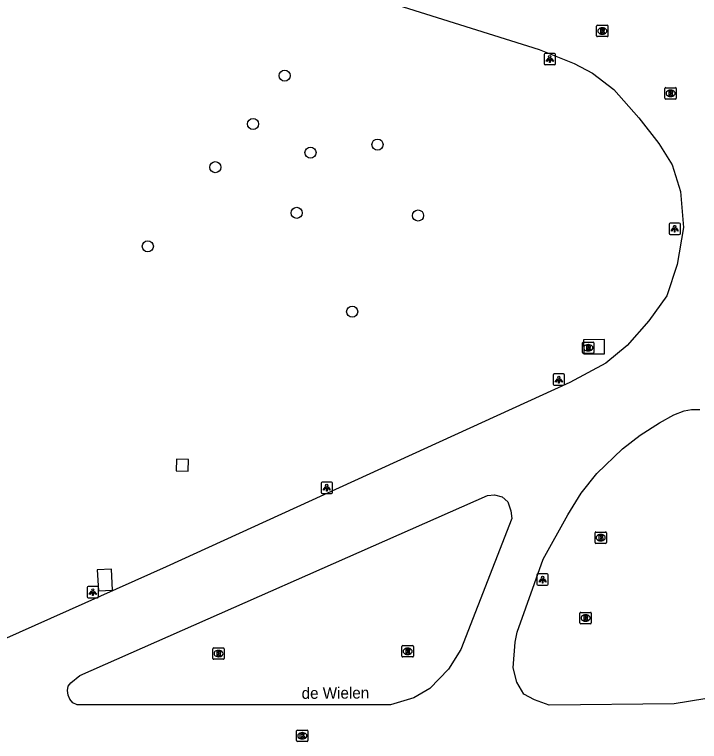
# Model space of a CAD drawing. Extents: x 161477 to 163040, y 383680 to 384868.
# Drawn here: x 161751.9 to 161812.2, y 384190.3 to 384254.4 of the extents above; entities that cross this region are included whole.
import ezdxf

# ---------------------------------------------------------------- set-up
doc = ezdxf.new("R2010")
doc.units = 0
for name, color, linetype in [('IMGEO_Boom', 7, 'Continuous'), ('IMGEO_Brandkraan', 7, 'Continuous'), ('IMGEO_Kolk', 7, 'Continuous'), ('IMGEO_Lage_trafo', 7, 'Continuous'), ('IMGEO_Lichtpunt', 7, 'Continuous'), ('IMGEO_Openbare_ruimte_label', 7, 'Continuous'), ('IMGEO_Rijbaan_lokaal_gesloten', 7, 'Continuous'), ('IMGEO_Rioolput', 7, 'Continuous'), ('IMGEO_Voetpad_gesloten', 7, 'Continuous')]:
    doc.layers.add(name, color=color, linetype=linetype)

msp = doc.modelspace()

# ---------------------------------------------------------------- linework, layer by layer
at = {"layer": 'IMGEO_Boom'}
for centre in [(161775.696, 384248.985), (161772.921, 384244.729), (161783.878, 384242.91), (161777.975, 384242.204), (161769.594, 384240.919), (161776.761, 384236.894), (161787.45, 384236.66), (161763.649, 384233.95), (161781.646, 384228.19)]:
    msp.add_circle(centre, 0.489, dxfattribs=at)
at = {"layer": 'IMGEO_Brandkraan'}
for p, q in [((161803.029, 384207.854), (161803.029, 384208.706)), ((161803.104, 384208.78), (161803.956, 384208.78)), ((161803.517, 384208.56), (161803.542, 384208.56)), ((161804.03, 384208.706), (161804.03, 384207.854)), ((161803.54, 384208), (161803.515, 384208)), ((161803.956, 384207.78), (161803.104, 384207.78))]:
    msp.add_line(p, q, dxfattribs=at)
for points in [[(161803.029, 384207.854), (161803.029, 384208.706)], [(161803.104, 384208.78), (161803.956, 384208.78)], [(161803.377, 384208.48), (161803.377, 384208.08), (161803.59, 384208.08)], [(161803.608, 384208.48), (161803.377, 384208.48)], [(161804.03, 384208.706), (161804.03, 384207.854)], [(161803.556, 384208.399), (161803.502, 384208.399), (161803.502, 384208.323)], [(161803.502, 384208.323), (161803.555, 384208.323)], [(161803.564, 384208.247), (161803.502, 384208.247), (161803.502, 384208.166)], [(161803.502, 384208.166), (161803.564, 384208.166)], [(161803.956, 384207.78), (161803.104, 384207.78)]]:
    msp.add_lwpolyline(points, dxfattribs=at)
for centre, radius, start, end in [((161803.106, 384208.704), 0.0765, 91.55205, 178.44795), ((161803.106, 384208.704), 0.0765, 91.55205, 178.44795), ((161803.612, 384208.335), 0.145, 59.4692, 91.53667), ((161803.637, 384208.382), 0.0922, 285.51372, 58.15012), ((161803.954, 384208.704), 0.0765, 1.55205, 88.44795), ((161803.954, 384208.704), 0.0765, 1.55205, 88.44795), ((161803.106, 384207.856), 0.0765, 181.55205, 268.44795), ((161803.106, 384207.856), 0.0765, 181.55205, 268.44795), ((161803.557, 384208.361), 0.0379, 267.82845, 90.93552), ((161803.565, 384208.206), 0.0404, 269.87594, 90.50774), ((161803.596, 384208.331), 0.251, 268.66757, 293.53466), ((161803.642, 384208.19), 0.105, 301.31148, 78.98903), ((161803.954, 384207.856), 0.0765, 271.55205, 358.44795), ((161803.954, 384207.856), 0.0765, 271.55205, 358.44795)]:
    msp.add_arc(centre, radius, start, end, dxfattribs=at)
for centre, major_axis, ratio, start_param, end_param in [((161803.516, 384208.28), (-0.387, 0.002), 0.722429, 4.712389, 7.853982), ((161803.541, 384208.28), (-0.39, 0.002), 0.717154, 1.570796, 4.712389)]:
    msp.add_ellipse(centre, major_axis=major_axis, ratio=ratio, start_param=start_param, end_param=end_param, dxfattribs=at)
at = {"layer": 'IMGEO_Kolk'}
for p, q in [((161776.752, 384190.402), (161776.752, 384191.254)), ((161776.827, 384191.328), (161777.679, 384191.328)), ((161777.753, 384191.254), (161777.753, 384190.402)), ((161777.263, 384190.548), (161777.238, 384190.548)), ((161777.24, 384191.108), (161777.265, 384191.108)), ((161777.679, 384190.328), (161776.827, 384190.328))]:
    msp.add_line(p, q, dxfattribs=at)
for points in [[(161776.752, 384190.402), (161776.752, 384191.254)], [(161776.827, 384191.328), (161777.679, 384191.328)], [(161777.753, 384191.254), (161777.753, 384190.402)], [(161777.073, 384191.028), (161777.196, 384191.028), (161777.196, 384190.877), (161777.326, 384191.028), (161777.49, 384191.028), (161777.344, 384190.877), (161777.497, 384190.628), (161777.345, 384190.628), (161777.26, 384190.792), (161777.196, 384190.725), (161777.196, 384190.628), (161777.073, 384190.628), (161777.073, 384191.028)], [(161777.679, 384190.328), (161776.827, 384190.328)]]:
    msp.add_lwpolyline(points, dxfattribs=at)
for centre, start, end in [((161776.829, 384191.252), 91.55205, 178.44795), ((161776.829, 384191.252), 91.55205, 178.44795), ((161777.677, 384191.252), 1.55205, 88.44795), ((161777.677, 384191.252), 1.55205, 88.44795), ((161776.829, 384190.404), 181.55205, 268.44795), ((161776.829, 384190.404), 181.55205, 268.44795), ((161777.677, 384190.404), 271.55205, 358.44795), ((161777.677, 384190.404), 271.55205, 358.44795)]:
    msp.add_arc(centre, 0.0765, start, end, dxfattribs=at)
for centre, major_axis, ratio, start_param, end_param in [((161777.239, 384190.828), (-0.387, 0.002), 0.722429, 4.712389, 7.853982), ((161777.264, 384190.828), (-0.39, 0.002), 0.717154, 1.570796, 4.712389)]:
    msp.add_ellipse(centre, major_axis=major_axis, ratio=ratio, start_param=start_param, end_param=end_param, dxfattribs=at)
at = {"layer": 'IMGEO_Lage_trafo'}
for points in [[(161802.028, 384224.465), (161803.866, 384224.489), (161803.85, 384225.739), (161802.012, 384225.715), (161802.028, 384224.465)], [(161759.307, 384203.601), (161760.555, 384203.67), (161760.452, 384205.503), (161759.204, 384205.434), (161759.307, 384203.601)]]:
    msp.add_lwpolyline(points, dxfattribs=at)
at = {"layer": 'IMGEO_Lichtpunt'}
for p, q in [((161798.546, 384250.852), (161798.546, 384250.045)), ((161798.546, 384250.852), (161798.546, 384250.045)), ((161799.448, 384250.947), (161798.64, 384250.947)), ((161799.448, 384250.947), (161798.64, 384250.947)), ((161799.542, 384250.045), (161799.542, 384250.852)), ((161799.542, 384250.045), (161799.542, 384250.852)), ((161798.64, 384249.951), (161799.448, 384249.951)), ((161798.64, 384249.951), (161799.448, 384249.951)), ((161810.448, 384235.994), (161809.64, 384235.994)), ((161810.448, 384235.994), (161809.64, 384235.994)), ((161809.546, 384235.899), (161809.546, 384235.092)), ((161809.546, 384235.899), (161809.546, 384235.092)), ((161810.542, 384235.092), (161810.542, 384235.899)), ((161810.542, 384235.092), (161810.542, 384235.899)), ((161809.64, 384234.998), (161810.448, 384234.998)), ((161809.64, 384234.998), (161810.448, 384234.998)), ((161799.344, 384222.609), (161799.344, 384221.802)), ((161799.344, 384222.609), (161799.344, 384221.802)), ((161800.246, 384222.704), (161799.438, 384222.704)), ((161800.246, 384222.704), (161799.438, 384222.704)), ((161800.34, 384221.802), (161800.34, 384222.609)), ((161800.34, 384221.802), (161800.34, 384222.609)), ((161799.438, 384221.708), (161800.246, 384221.708)), ((161799.438, 384221.708), (161800.246, 384221.708)), ((161778.909, 384213.087), (161778.909, 384212.28)), ((161778.909, 384213.087), (161778.909, 384212.28)), ((161779.811, 384213.182), (161779.003, 384213.182)), ((161779.811, 384213.182), (161779.003, 384213.182)), ((161779.905, 384212.28), (161779.905, 384213.087)), ((161779.905, 384212.28), (161779.905, 384213.087)), ((161779.003, 384212.186), (161779.811, 384212.186)), ((161779.003, 384212.186), (161779.811, 384212.186)), ((161797.917, 384204.993), (161797.917, 384204.186)), ((161797.917, 384204.993), (161797.917, 384204.186)), ((161798.819, 384205.088), (161798.011, 384205.088)), ((161798.819, 384205.088), (161798.011, 384205.088)), ((161798.913, 384204.186), (161798.913, 384204.993)), ((161798.913, 384204.186), (161798.913, 384204.993)), ((161759.213, 384203.985), (161758.405, 384203.985)), ((161759.213, 384203.985), (161758.405, 384203.985)), ((161798.011, 384204.092), (161798.819, 384204.092)), ((161798.011, 384204.092), (161798.819, 384204.092)), ((161758.311, 384203.89), (161758.311, 384203.083)), ((161758.311, 384203.89), (161758.311, 384203.083)), ((161759.307, 384203.083), (161759.307, 384203.89)), ((161759.307, 384203.083), (161759.307, 384203.89)), ((161758.405, 384202.989), (161759.213, 384202.989)), ((161758.405, 384202.989), (161759.213, 384202.989))]:
    msp.add_line(p, q, dxfattribs=at)
for points in [[(161798.92, 384250.516), (161798.959, 384250.488), (161798.771, 384250.226), (161798.733, 384250.253), (161798.92, 384250.516)], [(161799.022, 384250.468), (161799.069, 384250.468), (161799.069, 384250.146), (161799.022, 384250.146), (161799.022, 384250.468)], [(161799.132, 384250.488), (161799.17, 384250.515), (161799.357, 384250.253), (161799.318, 384250.225), (161799.132, 384250.488)], [(161809.92, 384235.563), (161809.959, 384235.535), (161809.771, 384235.273), (161809.733, 384235.3), (161809.92, 384235.563)], [(161810.022, 384235.515), (161810.069, 384235.515), (161810.069, 384235.193), (161810.022, 384235.193), (161810.022, 384235.515)], [(161810.132, 384235.535), (161810.17, 384235.562), (161810.357, 384235.3), (161810.318, 384235.272), (161810.132, 384235.535)], [(161799.718, 384222.273), (161799.757, 384222.245), (161799.569, 384221.983), (161799.531, 384222.01), (161799.718, 384222.273)], [(161799.82, 384222.225), (161799.867, 384222.225), (161799.867, 384221.903), (161799.82, 384221.903), (161799.82, 384222.225)], [(161799.93, 384222.245), (161799.968, 384222.272), (161800.155, 384222.01), (161800.116, 384221.982), (161799.93, 384222.245)], [(161779.283, 384212.751), (161779.322, 384212.723), (161779.134, 384212.461), (161779.096, 384212.488), (161779.283, 384212.751)], [(161779.385, 384212.703), (161779.432, 384212.703), (161779.432, 384212.381), (161779.385, 384212.381), (161779.385, 384212.703)], [(161779.495, 384212.723), (161779.533, 384212.75), (161779.72, 384212.488), (161779.681, 384212.46), (161779.495, 384212.723)], [(161798.291, 384204.657), (161798.33, 384204.629), (161798.142, 384204.367), (161798.104, 384204.394), (161798.291, 384204.657)], [(161798.503, 384204.629), (161798.541, 384204.656), (161798.728, 384204.394), (161798.689, 384204.366), (161798.503, 384204.629)], [(161798.393, 384204.609), (161798.44, 384204.609), (161798.44, 384204.287), (161798.393, 384204.287), (161798.393, 384204.609)], [(161758.685, 384203.554), (161758.724, 384203.526), (161758.536, 384203.264), (161758.498, 384203.291), (161758.685, 384203.554)], [(161758.787, 384203.506), (161758.834, 384203.506), (161758.834, 384203.184), (161758.787, 384203.184), (161758.787, 384203.506)], [(161758.897, 384203.526), (161758.935, 384203.553), (161759.122, 384203.291), (161759.083, 384203.263), (161758.897, 384203.526)]]:
    msp.add_lwpolyline(points, dxfattribs=at)
for centre in [(161799.045, 384250.65), (161810.045, 384235.697), (161799.843, 384222.407), (161779.408, 384212.885), (161798.416, 384204.791), (161758.81, 384203.688)]:
    msp.add_circle(centre, 0.0994, dxfattribs=at)
for centre, start, end in [((161798.64, 384250.852), 90, 180), ((161798.64, 384250.852), 90, 180), ((161799.448, 384250.852), 0, 90), ((161799.448, 384250.852), 0, 90), ((161798.64, 384250.045), 180, 270), ((161798.64, 384250.045), 180, 270), ((161799.448, 384250.045), 270, 0), ((161799.448, 384250.045), 270, 360), ((161809.64, 384235.899), 90, 180), ((161809.64, 384235.899), 90, 180), ((161810.448, 384235.899), 0, 90), ((161810.448, 384235.899), 0, 90), ((161809.64, 384235.092), 180, 270), ((161809.64, 384235.092), 180, 270), ((161810.448, 384235.092), 270, 0), ((161810.448, 384235.092), 270, 360), ((161799.438, 384222.609), 90, 180), ((161799.438, 384222.609), 90, 180), ((161800.246, 384222.609), 0, 90), ((161800.246, 384222.609), 0, 90), ((161799.438, 384221.802), 180, 270), ((161799.438, 384221.802), 180, 270), ((161800.246, 384221.802), 270, 0), ((161800.246, 384221.802), 270, 360), ((161779.003, 384213.087), 90, 180), ((161779.003, 384213.087), 90, 180), ((161779.811, 384213.087), 0, 90), ((161779.811, 384213.087), 0, 90), ((161779.003, 384212.28), 180, 270), ((161779.003, 384212.28), 180, 270), ((161779.811, 384212.28), 270, 0), ((161779.811, 384212.28), 270, 360), ((161798.011, 384204.993), 90, 180), ((161798.011, 384204.993), 90, 180), ((161798.819, 384204.993), 0, 90), ((161798.819, 384204.993), 0, 90), ((161758.405, 384203.89), 90, 180), ((161758.405, 384203.89), 90, 180), ((161759.213, 384203.89), 0, 90), ((161759.213, 384203.89), 0, 90), ((161798.011, 384204.186), 180, 270), ((161798.011, 384204.186), 180, 270), ((161798.819, 384204.186), 270, 0), ((161798.819, 384204.186), 270, 360), ((161758.405, 384203.083), 180, 270), ((161758.405, 384203.083), 180, 270), ((161759.213, 384203.083), 270, 0), ((161759.213, 384203.083), 270, 360)]:
    msp.add_arc(centre, 0.0946, start, end, dxfattribs=at)
at = {"layer": 'IMGEO_Rijbaan_lokaal_gesloten'}
for points in [[(161756.674, 384264.323), (161798.102, 384251.287), (161801.197, 384250.04), (161802.793, 384249.215), (161804.691, 384247.773), (161806.876, 384245.277), (161808.636, 384243.002), (161809.809, 384241.12), (161810.562, 384238.772), (161810.827, 384235.617), (161810.252, 384232.34), (161809.351, 384229.582), (161807.757, 384227.377), (161805.847, 384225.201), (161803.993, 384223.644), (161800.806, 384221.962), (161765.263, 384205.726), (161734.934, 384192.171)], [(161800.628, 384210.303), (161801.8, 384212.194), (161803.192, 384213.927), (161805.441, 384216.097), (161807.015, 384217.304), (161808.697, 384218.393), (161809.977, 384219.108), (161810.875, 384219.454), (161811.525, 384219.577), (161812.253, 384219.58)], [(161756.87, 384195.493), (161757.674, 384196.129), (161793.552, 384212.004), (161794.189, 384212.041), (161794.854, 384211.875), (161795.338, 384211.448), (161795.613, 384210.631), (161795.707, 384209.98), (161791.199, 384198.416), (161790.115, 384196.711), (161788.477, 384195.006), (161787.06, 384194.165), (161785.033, 384193.567), (161757.44, 384193.567), (161757.044, 384193.721), (161756.784, 384194.047), (161756.632, 384194.408), (161756.588, 384194.827), (161756.646, 384195.189), (161756.87, 384195.493)], [(161812.711, 384194.083), (161810.004, 384193.656), (161798.988, 384193.52), (161797.686, 384193.988), (161796.75, 384194.506), (161796.143, 384195.557), (161795.814, 384196.815), (161795.991, 384199.08), (161796.169, 384199.967), (161798.462, 384206.387), (161800.628, 384210.303)]]:
    msp.add_lwpolyline(points, dxfattribs=at)
at = {"layer": 'IMGEO_Rioolput'}
for p, q in [((161803.169, 384252.494), (161803.169, 384253.346)), ((161803.244, 384253.42), (161804.096, 384253.42)), ((161804.17, 384253.346), (161804.17, 384252.494)), ((161803.657, 384253.2), (161803.682, 384253.2)), ((161804.096, 384252.42), (161803.244, 384252.42)), ((161803.68, 384252.64), (161803.655, 384252.64)), ((161809.182, 384246.998), (161809.182, 384247.85)), ((161809.257, 384247.924), (161810.109, 384247.924)), ((161809.67, 384247.704), (161809.695, 384247.704)), ((161810.183, 384247.85), (161810.183, 384246.998)), ((161810.109, 384246.924), (161809.257, 384246.924)), ((161809.693, 384247.144), (161809.668, 384247.144)), ((161801.932, 384224.583), (161801.932, 384225.435)), ((161802.007, 384225.509), (161802.859, 384225.509)), ((161802.42, 384225.289), (161802.445, 384225.289)), ((161802.933, 384225.435), (161802.933, 384224.583)), ((161802.859, 384224.509), (161802.007, 384224.509)), ((161802.443, 384224.729), (161802.418, 384224.729)), ((161801.699, 384200.774), (161801.699, 384201.626)), ((161801.774, 384201.7), (161802.626, 384201.7)), ((161802.187, 384201.48), (161802.212, 384201.48)), ((161802.7, 384201.626), (161802.7, 384200.774)), ((161802.21, 384200.92), (161802.185, 384200.92)), ((161802.626, 384200.7), (161801.774, 384200.7)), ((161769.379, 384197.644), (161769.379, 384198.496)), ((161769.454, 384198.57), (161770.306, 384198.57)), ((161769.867, 384198.35), (161769.892, 384198.35)), ((161770.38, 384198.496), (161770.38, 384197.644)), ((161786.029, 384197.844), (161786.029, 384198.696)), ((161786.104, 384198.77), (161786.956, 384198.77)), ((161786.517, 384198.55), (161786.542, 384198.55)), ((161787.03, 384198.696), (161787.03, 384197.844)), ((161770.306, 384197.57), (161769.454, 384197.57)), ((161769.89, 384197.79), (161769.865, 384197.79)), ((161786.956, 384197.77), (161786.104, 384197.77)), ((161786.54, 384197.99), (161786.515, 384197.99))]:
    msp.add_line(p, q, dxfattribs=at)
for points in [[(161803.169, 384252.494), (161803.169, 384253.346)], [(161803.244, 384253.42), (161804.096, 384253.42)], [(161804.17, 384253.346), (161804.17, 384252.494)], [(161803.758, 384253.118), (161803.506, 384253.12), (161803.506, 384252.72)], [(161803.506, 384252.72), (161803.63, 384252.72), (161803.63, 384252.882), (161803.641, 384252.882)], [(161803.684, 384253.039), (161803.63, 384253.039), (161803.63, 384252.958)], [(161803.63, 384252.958), (161803.682, 384252.958)], [(161803.688, 384252.853), (161803.759, 384252.72), (161803.899, 384252.72), (161803.834, 384252.846)], [(161804.096, 384252.42), (161803.244, 384252.42)], [(161809.182, 384246.998), (161809.182, 384247.85)], [(161809.257, 384247.924), (161810.109, 384247.924)], [(161809.771, 384247.622), (161809.519, 384247.624), (161809.519, 384247.224)], [(161809.697, 384247.543), (161809.643, 384247.543), (161809.643, 384247.462)], [(161810.183, 384247.85), (161810.183, 384246.998)], [(161810.109, 384246.924), (161809.257, 384246.924)], [(161809.519, 384247.224), (161809.643, 384247.224), (161809.643, 384247.386), (161809.654, 384247.386)], [(161809.643, 384247.462), (161809.695, 384247.462)], [(161809.701, 384247.357), (161809.772, 384247.224), (161809.912, 384247.224), (161809.847, 384247.35)], [(161801.932, 384224.583), (161801.932, 384225.435)], [(161802.007, 384225.509), (161802.859, 384225.509)], [(161802.521, 384225.207), (161802.269, 384225.209), (161802.269, 384224.809)], [(161802.447, 384225.128), (161802.393, 384225.128), (161802.393, 384225.047)], [(161802.933, 384225.435), (161802.933, 384224.583)], [(161802.859, 384224.509), (161802.007, 384224.509)], [(161802.269, 384224.809), (161802.393, 384224.809), (161802.393, 384224.971), (161802.404, 384224.971)], [(161802.393, 384225.047), (161802.445, 384225.047)], [(161802.451, 384224.942), (161802.522, 384224.809), (161802.662, 384224.809), (161802.597, 384224.935)], [(161801.699, 384200.774), (161801.699, 384201.626)], [(161801.774, 384201.7), (161802.626, 384201.7)], [(161802.7, 384201.626), (161802.7, 384200.774)], [(161802.288, 384201.398), (161802.036, 384201.4), (161802.036, 384201)], [(161802.036, 384201), (161802.16, 384201), (161802.16, 384201.162), (161802.171, 384201.162)], [(161802.214, 384201.319), (161802.16, 384201.319), (161802.16, 384201.238)], [(161802.16, 384201.238), (161802.212, 384201.238)], [(161802.218, 384201.133), (161802.289, 384201), (161802.429, 384201), (161802.364, 384201.126)], [(161802.626, 384200.7), (161801.774, 384200.7)], [(161769.379, 384197.644), (161769.379, 384198.496)], [(161769.454, 384198.57), (161770.306, 384198.57)], [(161769.968, 384198.268), (161769.716, 384198.27), (161769.716, 384197.87)], [(161770.38, 384198.496), (161770.38, 384197.644)], [(161786.029, 384197.844), (161786.029, 384198.696)], [(161786.104, 384198.77), (161786.956, 384198.77)], [(161786.618, 384198.468), (161786.366, 384198.47), (161786.366, 384198.07)], [(161786.366, 384198.07), (161786.49, 384198.07), (161786.49, 384198.232), (161786.501, 384198.232)], [(161786.544, 384198.389), (161786.49, 384198.389), (161786.49, 384198.308)], [(161786.49, 384198.308), (161786.542, 384198.308)], [(161787.03, 384198.696), (161787.03, 384197.844)], [(161770.306, 384197.57), (161769.454, 384197.57)], [(161769.716, 384197.87), (161769.84, 384197.87), (161769.84, 384198.032), (161769.851, 384198.032)], [(161769.894, 384198.189), (161769.84, 384198.189), (161769.84, 384198.108)], [(161769.84, 384198.108), (161769.892, 384198.108)], [(161769.898, 384198.003), (161769.969, 384197.87), (161770.109, 384197.87), (161770.044, 384197.996)], [(161786.956, 384197.77), (161786.104, 384197.77)], [(161786.548, 384198.203), (161786.619, 384198.07), (161786.759, 384198.07), (161786.694, 384198.196)]]:
    msp.add_lwpolyline(points, dxfattribs=at)
for centre, radius, start, end in [((161803.246, 384253.344), 0.0765, 91.55205, 178.44795), ((161803.246, 384253.344), 0.0765, 91.55205, 178.44795), ((161804.094, 384253.344), 0.0765, 1.55205, 88.44795), ((161804.094, 384253.344), 0.0765, 1.55205, 88.44795), ((161803.64, 384252.829), 0.0533, 26.02933, 88.69889), ((161803.666, 384253.147), 0.19, 274.7715, 282.96867), ((161803.69, 384252.943), 0.0964, 77.00612, 93.18647), ((161803.704, 384253), 0.0378, 276.66336, 79.67722), ((161803.757, 384253.008), 0.109, 350.36119, 89.41601), ((161803.755, 384253.008), 0.112, 277.58423, 350.98172), ((161803.739, 384252.793), 0.108, 29.51342, 73.79051), ((161803.246, 384252.496), 0.0765, 181.55205, 268.44795), ((161803.246, 384252.496), 0.0765, 181.55205, 268.44795), ((161804.094, 384252.496), 0.0765, 271.55205, 358.44795), ((161804.094, 384252.496), 0.0765, 271.55205, 358.44795), ((161809.259, 384247.848), 0.0765, 91.55205, 178.44795), ((161809.259, 384247.848), 0.0765, 91.55205, 178.44795), ((161809.703, 384247.447), 0.0964, 77.00612, 93.18647), ((161809.717, 384247.504), 0.0378, 276.66336, 79.67722), ((161809.77, 384247.512), 0.109, 350.36119, 89.41601), ((161810.107, 384247.848), 0.0765, 1.55205, 88.44795), ((161810.107, 384247.848), 0.0765, 1.55205, 88.44795), ((161809.259, 384247), 0.0765, 181.55205, 268.44795), ((161809.259, 384247), 0.0765, 181.55205, 268.44795), ((161809.653, 384247.333), 0.0533, 26.02933, 88.69889), ((161809.679, 384247.651), 0.19, 274.7715, 282.96867), ((161809.768, 384247.512), 0.112, 277.58423, 350.98172), ((161809.752, 384247.297), 0.108, 29.51342, 73.79051), ((161810.107, 384247), 0.0765, 271.55205, 358.44795), ((161810.107, 384247), 0.0765, 271.55205, 358.44795), ((161802.009, 384225.433), 0.0765, 91.55205, 178.44795), ((161802.009, 384225.433), 0.0765, 91.55205, 178.44795), ((161802.453, 384225.032), 0.0964, 77.00612, 93.18647), ((161802.467, 384225.089), 0.0378, 276.66336, 79.67722), ((161802.52, 384225.097), 0.109, 350.36119, 89.41601), ((161802.857, 384225.433), 0.0765, 1.55205, 88.44795), ((161802.857, 384225.433), 0.0765, 1.55205, 88.44795), ((161802.009, 384224.585), 0.0765, 181.55205, 268.44795), ((161802.009, 384224.585), 0.0765, 181.55205, 268.44795), ((161802.403, 384224.918), 0.0533, 26.02933, 88.69889), ((161802.429, 384225.236), 0.19, 274.7715, 282.96867), ((161802.518, 384225.097), 0.112, 277.58423, 350.98172), ((161802.502, 384224.882), 0.108, 29.51342, 73.79051), ((161802.857, 384224.585), 0.0765, 271.55205, 358.44795), ((161802.857, 384224.585), 0.0765, 271.55205, 358.44795), ((161801.776, 384201.624), 0.0765, 91.55205, 178.44795), ((161801.776, 384201.624), 0.0765, 91.55205, 178.44795), ((161802.624, 384201.624), 0.0765, 1.55205, 88.44795), ((161802.624, 384201.624), 0.0765, 1.55205, 88.44795), ((161801.776, 384200.776), 0.0765, 181.55205, 268.44795), ((161801.776, 384200.776), 0.0765, 181.55205, 268.44795), ((161802.17, 384201.109), 0.0533, 26.02933, 88.69889), ((161802.196, 384201.427), 0.19, 274.7715, 282.96867), ((161802.22, 384201.223), 0.0964, 77.00612, 93.18647), ((161802.234, 384201.28), 0.0378, 276.66336, 79.67722), ((161802.287, 384201.288), 0.109, 350.36119, 89.41601), ((161802.285, 384201.288), 0.112, 277.58423, 350.98172), ((161802.269, 384201.073), 0.108, 29.51342, 73.79051), ((161802.624, 384200.776), 0.0765, 271.55205, 358.44795), ((161802.624, 384200.776), 0.0765, 271.55205, 358.44795), ((161769.456, 384198.494), 0.0765, 91.55205, 178.44795), ((161769.456, 384198.494), 0.0765, 91.55205, 178.44795), ((161769.967, 384198.158), 0.109, 350.36119, 89.41601), ((161770.304, 384198.494), 0.0765, 1.55205, 88.44795), ((161770.304, 384198.494), 0.0765, 1.55205, 88.44795), ((161786.106, 384198.694), 0.0765, 91.55205, 178.44795), ((161786.106, 384198.694), 0.0765, 91.55205, 178.44795), ((161786.5, 384198.179), 0.0533, 26.02933, 88.69889), ((161786.526, 384198.497), 0.19, 274.7715, 282.96867), ((161786.55, 384198.293), 0.0964, 77.00612, 93.18647), ((161786.564, 384198.35), 0.0378, 276.66336, 79.67722), ((161786.617, 384198.358), 0.109, 350.36119, 89.41601), ((161786.615, 384198.358), 0.112, 277.58423, 350.98172), ((161786.599, 384198.143), 0.108, 29.51342, 73.79051), ((161786.954, 384198.694), 0.0765, 1.55205, 88.44795), ((161786.954, 384198.694), 0.0765, 1.55205, 88.44795), ((161769.456, 384197.646), 0.0765, 181.55205, 268.44795), ((161769.456, 384197.646), 0.0765, 181.55205, 268.44795), ((161769.85, 384197.979), 0.0533, 26.02933, 88.69889), ((161769.876, 384198.297), 0.19, 274.7715, 282.96867), ((161769.9, 384198.093), 0.0964, 77.00612, 93.18647), ((161769.914, 384198.15), 0.0378, 276.66336, 79.67722), ((161769.965, 384198.158), 0.112, 277.58423, 350.98172), ((161769.949, 384197.943), 0.108, 29.51342, 73.79051), ((161770.304, 384197.646), 0.0765, 271.55205, 358.44795), ((161770.304, 384197.646), 0.0765, 271.55205, 358.44795), ((161786.106, 384197.846), 0.0765, 181.55205, 268.44795), ((161786.106, 384197.846), 0.0765, 181.55205, 268.44795), ((161786.954, 384197.846), 0.0765, 271.55205, 358.44795), ((161786.954, 384197.846), 0.0765, 271.55205, 358.44795)]:
    msp.add_arc(centre, radius, start, end, dxfattribs=at)
for centre, major_axis, ratio, start_param, end_param in [((161803.656, 384252.92), (-0.387, 0.002), 0.722429, 4.712389, 7.853982), ((161803.681, 384252.92), (-0.39, 0.002), 0.717154, 1.570796, 4.712389), ((161809.669, 384247.424), (-0.387, 0.002), 0.722429, 4.712389, 7.853982), ((161809.694, 384247.424), (-0.39, 0.002), 0.717154, 1.570796, 4.712389), ((161802.419, 384225.009), (-0.387, 0.002), 0.722429, 4.712389, 7.853982), ((161802.444, 384225.009), (-0.39, 0.002), 0.717154, 1.570796, 4.712389), ((161802.186, 384201.2), (-0.387, 0.002), 0.722429, 4.712389, 7.853982), ((161802.211, 384201.2), (-0.39, 0.002), 0.717154, 1.570796, 4.712389), ((161769.866, 384198.07), (-0.387, 0.002), 0.722429, 4.712389, 7.853982), ((161769.891, 384198.07), (-0.39, 0.002), 0.717154, 1.570796, 4.712389), ((161786.516, 384198.27), (-0.387, 0.002), 0.722429, 4.712389, 7.853982), ((161786.541, 384198.27), (-0.39, 0.002), 0.717154, 1.570796, 4.712389)]:
    msp.add_ellipse(centre, major_axis=major_axis, ratio=ratio, start_param=start_param, end_param=end_param, dxfattribs=at)
at = {"layer": 'IMGEO_Voetpad_gesloten'}
msp.add_lwpolyline([(161767.223, 384215.18), (161766.183, 384215.206), (161766.158, 384214.173), (161767.198, 384214.147), (161767.223, 384215.18)], dxfattribs=at)

# ---------------------------------------------------------------- texts
at = {"layer": 'IMGEO_Openbare_ruimte_label'}
msp.add_text('de Wielen', height=1, rotation=0.40106, dxfattribs=at).set_placement((161777.2, 384194.078))

doc.saveas('drawing.dxf')
